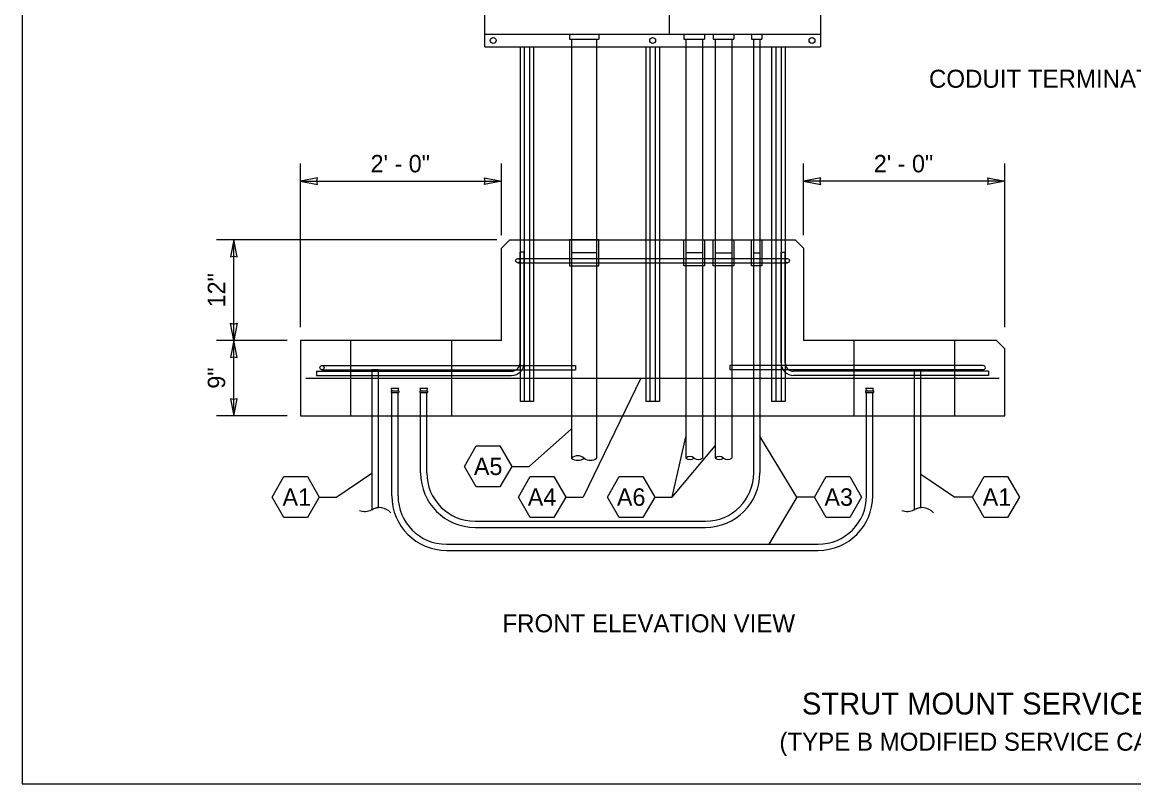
# Model space of a CAD drawing. Extents: x 99862 to 103151, y 100000 to 117076.
# Drawn here: x 99862 to 100882, y 103000 to 103698 of the extents above; entities that cross this region are included whole.
import ezdxf

# ---------------------------------------------------------------- set-up
doc = ezdxf.new("R2010")
doc.units = 0
for name, color, linetype in [('Default', 7, 'Continuous'), ('Level 1', 7, 'Continuous'), ('Level 11', 7, 'Continuous'), ('Level 15', 7, 'Continuous'), ('Level 20', 7, 'Continuous'), ('Level 40', 7, 'Continuous'), ('Level 60', 7, 'Continuous')]:
    doc.layers.add(name, color=color, linetype=linetype)

msp = doc.modelspace()

# ---------------------------------------------------------------- linework, layer by layer
at = {"layer": 'Default'}
for p, q in [((100316.7, 103481.1), (100564, 103481.1)), ((100318.7, 103385.5), (100318.7, 103486.9)), ((100322.5, 103486.9), (100318.7, 103486.9)), ((100322.5, 103385.5), (100322.5, 103486.9)), ((100558.2, 103385.5), (100558.2, 103486.9)), ((100558.2, 103486.9), (100562, 103486.9)), ((100562, 103385.5), (100562, 103486.9)), ((100316.7, 103477.2), (100564, 103477.2)), ((100132.1, 103377.9), (100132.1, 103374)), ((100132.1, 103377.9), (100311, 103377.9)), ((100137, 103383.1), (100369.5, 103383.1)), ((100137, 103379.2), (100369.5, 103379.2)), ((100369.5, 103383.1), (100369.5, 103379.2)), ((100511.2, 103383.1), (100511.2, 103379.2)), ((100743.7, 103383.1), (100511.2, 103383.1)), ((100743.7, 103379.2), (100511.2, 103379.2)), ((100748.6, 103377.9), (100569.7, 103377.9)), ((100748.6, 103377.9), (100748.6, 103374)), ((100132.1, 103374), (100311, 103374)), ((100748.6, 103374), (100569.7, 103374))]:
    msp.add_line(p, q, dxfattribs=at)
for centre in [(100316.7, 103479.2), (100564, 103479.2), (100137, 103381.1)]:
    msp.add_circle(centre, 1.92, dxfattribs=at)
for centre, radius, start, end in [((100311, 103385.5), 11.5, 270, 0), ((100311, 103385.5), 7.7, 270, 0), ((100569.7, 103385.5), 11.5, 180, 270), ((100569.7, 103385.5), 7.7, 180, 270), ((100743.7, 103381.1), 1.92, 270, 90)]:
    msp.add_arc(centre, radius, start, end, dxfattribs=at)
at = {"layer": 'Level 1'}
for p, q in [((100364, 103687), (100364, 103682.4)), ((100391, 103687), (100391, 103682.4)), ((100468.9, 103687), (100468.9, 103682.4)), ((100488.1, 103687), (100488.1, 103682.4)), ((100495.8, 103687), (100495.8, 103682.4)), ((100515, 103687), (100515, 103682.4)), ((100531.1, 103687), (100531.1, 103682.4)), ((100540.7, 103687), (100540.7, 103682.4)), ((100364, 103682.4), (100391, 103682.4)), ((100366, 103682.4), (100366, 103498.4)), ((100389, 103682.4), (100389, 103498.4)), ((100468.9, 103682.4), (100488.1, 103682.4)), ((100470.8, 103682.4), (100470.8, 103498.4)), ((100486.2, 103682.4), (100486.2, 103498.4)), ((100495.8, 103682.4), (100515, 103682.4)), ((100497.7, 103682.4), (100497.7, 103498.4)), ((100513.1, 103682.4), (100513.1, 103498.4)), ((100531.1, 103682.4), (100540.7, 103682.4)), ((100533, 103682.4), (100533, 103498.4)), ((100538.8, 103682.4), (100538.8, 103498.4)), ((100366, 103498.4), (100366, 103298.2)), ((100389, 103498.4), (100389, 103298.2)), ((100470.8, 103498.4), (100470.8, 103298.2)), ((100486.2, 103498.4), (100486.2, 103298.2)), ((100497.7, 103498.4), (100497.7, 103298.2)), ((100513.1, 103498.4), (100513.1, 103298.2)), ((100533, 103498.4), (100533, 103284.6)), ((100538.8, 103498.4), (100538.8, 103284.6)), ((100389, 103486.5), (100366, 103486.5)), ((100486.2, 103486.5), (100470.8, 103486.5)), ((100497.7, 103486.5), (100513.1, 103486.5)), ((100533, 103486.5), (100538.8, 103486.5)), ((100200.4, 103362.3), (100207.6, 103362.3)), ((100200.4, 103359.9), (100200.4, 103358.2)), ((100200.4, 103359.9), (100207.6, 103359.9)), ((100200.4, 103358.2), (100207.6, 103358.2)), ((100201.1, 103360.6), (100201.1, 103359.9)), ((100201.1, 103263.5), (100201.1, 103358.2)), ((100206.9, 103360.6), (100206.9, 103359.9)), ((100206.9, 103263.5), (100206.9, 103358.2)), ((100207.6, 103359.9), (100207.6, 103358.2)), ((100226.7, 103362.3), (100233.9, 103362.3)), ((100226.7, 103359.9), (100226.7, 103358.2)), ((100226.7, 103359.9), (100233.9, 103359.9)), ((100226.7, 103358.2), (100233.9, 103358.2)), ((100227.5, 103360.6), (100227.5, 103359.9)), ((100227.5, 103284.6), (100227.5, 103358.2)), ((100233.2, 103360.6), (100233.2, 103359.9)), ((100233.2, 103284.6), (100233.2, 103358.2)), ((100233.9, 103359.9), (100233.9, 103358.2)), ((100635.8, 103362.3), (100643, 103362.3)), ((100635.8, 103359.9), (100635.8, 103358.2)), ((100635.8, 103359.9), (100643, 103359.9)), ((100635.8, 103358.2), (100643, 103358.2)), ((100636.5, 103360.6), (100636.5, 103359.9)), ((100636.5, 103261.9), (100636.5, 103358.2)), ((100642.3, 103360.6), (100642.3, 103359.9)), ((100642.3, 103261.8), (100642.3, 103358.2)), ((100643, 103359.9), (100643, 103358.2)), ((100277.5, 103240.4), (100488.8, 103240.4)), ((100277.5, 103234.6), (100488.8, 103234.6)), ((100251.1, 103219.2), (100592.3, 103219.2)), ((100251.1, 103213.4), (100592.3, 103213.4))]:
    msp.add_line(p, q, dxfattribs=at)
for points in [[(99862, 102999.5), (103151, 102999.5), (103151, 105075.5), (99862, 105075.5)], [(100364, 103474.6), (100391, 103474.6), (100391, 103498.4), (100364, 103498.4)], [(100488.1, 103474.6), (100468.9, 103474.6), (100468.9, 103498.4), (100488.1, 103498.4)], [(100495.8, 103498.4), (100515, 103498.4), (100515, 103474.6), (100495.8, 103474.6)], [(100531.1, 103498.4), (100540.7, 103498.4), (100540.7, 103474.6), (100531.1, 103474.6)], [(100182.6, 103379.2), (100182.6, 103250.8), (100184.7, 103251.9), (100186.8, 103252.4), (100188.8, 103252.7), (100188.8, 103379.2)], [(100680.3, 103379.2), (100680.3, 103250.8), (100682.5, 103251.9), (100684.5, 103252.4), (100686.5, 103252.7), (100686.5, 103379.2)]]:
    msp.add_lwpolyline(points, close=True, dxfattribs=at)
for centre, radius, start, end in [((100198.7, 103360.6), 2.37, 0, 45.9402), ((100209.2, 103360.6), 2.37, 134.0598, 180), ((100225.1, 103360.6), 2.37, 0, 45.9402), ((100235.6, 103360.6), 2.37, 134.0598, 180), ((100634.2, 103360.6), 2.37, 0, 45.9402), ((100644.7, 103360.6), 2.37, 134.0598, 180), ((100371.7, 103291.1), 9.14, 50.8329, 129.1671), ((100371.7, 103305.3), 9.14, 230.8329, 309.1671), ((100383.3, 103305.3), 9.14, 230.8329, 309.1671), ((100474.7, 103293.5), 6.09, 50.8329, 129.1671), ((100474.7, 103302.9), 6.09, 230.8329, 309.1671), ((100482.4, 103302.9), 6.09, 230.8329, 309.1671), ((100501.5, 103293.5), 6.09, 50.8329, 129.1671), ((100501.5, 103302.9), 6.09, 230.8329, 309.1671), ((100509.2, 103302.9), 6.09, 230.8329, 309.1671), ((100277.5, 103284.6), 50, 180, 270), ((100277.5, 103284.6), 44.3, 180, 270), ((100488.8, 103284.6), 44.3, 270, 0), ((100488.8, 103284.6), 50, 270, 0), ((100251.1, 103263.5), 50, 180, 270), ((100251.1, 103263.5), 44.3, 180, 270), ((100592.3, 103263.5), 44.3, 270, 0), ((100592.3, 103263.5), 50, 270, 0), ((100176.2, 103263.9), 14.6, 250.7571, 295.3506), ((100189.8, 103238.6), 14.1, 42.3778, 121.1813), ((100673.9, 103263.9), 14.6, 250.7571, 295.3506), ((100687.5, 103238.6), 14.1, 42.3778, 121.1813)]:
    msp.add_arc(centre, radius, start, end, dxfattribs=at)
at = {"layer": 'Level 11'}
for p, q in [((100163.3, 103406.1), (100163.3, 103336.8)), ((100255.7, 103406.1), (100255.7, 103336.8)), ((100625, 103406.1), (100625, 103336.8)), ((100717.4, 103406.1), (100717.4, 103336.8))]:
    msp.add_line(p, q, dxfattribs=at)
for points in [[(100301.8, 103406.1), (100301.8, 103490.7), (100309.5, 103498.4)], [(100309.5, 103498.4), (100571.2, 103498.4)], [(100571.2, 103498.4), (100578.9, 103490.7), (100578.9, 103406.1)], [(100117.2, 103406.1), (100117.2, 103336.8)], [(100301.8, 103406.1), (100117.2, 103406.1)], [(100755.8, 103406.1), (100578.9, 103406.1)], [(100763.5, 103336.8), (100763.5, 103398.4), (100755.8, 103406.1)], [(100117.2, 103336.8), (100763.5, 103336.8)]]:
    msp.add_lwpolyline(points, dxfattribs=at)
at = {"layer": 'Level 15'}
for p, q in [((100117.2, 103418.1), (100117.2, 103568.2)), ((100301.8, 103502.7), (100301.8, 103568.2)), ((100578.9, 103502.7), (100578.9, 103568.2)), ((100763.5, 103418.1), (100763.5, 103568.2)), ((100117.2, 103552.2), (100301.8, 103552.2)), ((100763.5, 103552.2), (100578.9, 103552.2)), ((100297.5, 103498.4), (100040.2, 103498.4)), ((100056.2, 103406.1), (100056.2, 103498.4)), ((100105.2, 103406.1), (100040.2, 103406.1)), ((100056.2, 103336.8), (100056.2, 103406.1)), ((100429.5, 103371.4), (100376.6, 103262.4)), ((100105.2, 103336.8), (100040.2, 103336.8)), ((100327.1, 103290.6), (100366, 103324.9)), ((100458.3, 103262.4), (100470.8, 103317.6)), ((100572.8, 103262.4), (100538.8, 103318.4)), ((100458.3, 103262.4), (100497.7, 103309.3)), ((100311.1, 103290.6), (100327.1, 103290.6)), ((100182.6, 103283.9), (100150.5, 103262.4)), ((100686.5, 103283.3), (100717.7, 103262.4)), ((100134.5, 103262.4), (100150.5, 103262.4)), ((100360.6, 103262.4), (100376.6, 103262.4)), ((100442.3, 103262.4), (100458.3, 103262.4)), ((100572.8, 103262.4), (100547, 103219.2)), ((100588.8, 103262.4), (100572.8, 103262.4)), ((100733.7, 103262.4), (100717.7, 103262.4))]:
    msp.add_line(p, q, dxfattribs=at)
for points in [[(100117.2, 103552.2), (100132.9, 103549.2), (100132.2, 103552.2), (100132.9, 103555.3)], [(100301.8, 103552.2), (100286.1, 103549.2), (100286.8, 103552.2), (100286.1, 103555.3)], [(100578.9, 103552.2), (100594.6, 103549.2), (100593.9, 103552.2), (100594.6, 103555.3)], [(100763.5, 103552.2), (100747.8, 103549.2), (100748.5, 103552.2), (100747.8, 103555.3)], [(100056.2, 103498.4), (100053.1, 103482.7), (100056.2, 103483.4), (100059.3, 103482.7)], [(100056.2, 103406.1), (100053.1, 103421.8), (100056.2, 103421.1), (100059.3, 103421.8)], [(100056.2, 103406.1), (100053.1, 103390.3), (100056.2, 103391.1), (100059.3, 103390.3)], [(100056.2, 103336.8), (100059.3, 103352.5), (100056.2, 103351.8), (100053.1, 103352.5)]]:
    msp.add_lwpolyline(points, close=True, dxfattribs=at)
for centre in [(100294.1, 103681.2), (100440.4, 103681.2), (100586.6, 103681.2)]:
    msp.add_circle(centre, 2.69, dxfattribs=at)
at = {"layer": 'Level 20'}
for points in [[(100267.8, 103290.6), (100278.6, 103309.4), (100300.3, 103309.4), (100311.1, 103290.6), (100300.3, 103271.9), (100278.6, 103271.9), (100267.8, 103290.6)], [(100091.2, 103262.4), (100102.1, 103281.2), (100123.7, 103281.2), (100134.5, 103262.4), (100123.7, 103243.7), (100102.1, 103243.7), (100091.2, 103262.4)], [(100317.3, 103262.4), (100328.1, 103281.2), (100349.8, 103281.2), (100360.6, 103262.4), (100349.8, 103243.7), (100328.1, 103243.7), (100317.3, 103262.4)], [(100399, 103262.4), (100409.8, 103281.2), (100431.4, 103281.2), (100442.3, 103262.4), (100431.4, 103243.7), (100409.8, 103243.7), (100399, 103262.4)], [(100588.8, 103262.4), (100599.6, 103281.2), (100621.3, 103281.2), (100632.1, 103262.4), (100621.3, 103243.7), (100599.6, 103243.7), (100588.8, 103262.4)], [(100733.7, 103262.4), (100744.5, 103281.2), (100766.1, 103281.2), (100776.9, 103262.4), (100766.1, 103243.7), (100744.5, 103243.7), (100733.7, 103262.4)]]:
    msp.add_lwpolyline(points, dxfattribs=at)
at = {"layer": 'Level 40'}
for p, q in [((100286.5, 103675.4), (100286.5, 103987.1)), ((100455.7, 103687), (100455.7, 103987.1)), ((100594.3, 103987.1), (100594.3, 103675.4)), ((100286.5, 103687), (100594.3, 103687)), ((100286.5, 103675.4), (100594.3, 103675.4)), ((100318.7, 103675.4), (100318.7, 103498.4)), ((100322.5, 103675.4), (100322.5, 103498.4)), ((100327.4, 103675.4), (100327.4, 103498.4)), ((100331.2, 103675.4), (100331.2, 103498.4)), ((100434.1, 103675.4), (100434.1, 103498.4)), ((100437.9, 103675.4), (100437.9, 103498.4)), ((100442.8, 103675.4), (100442.8, 103498.4)), ((100446.6, 103675.4), (100446.6, 103498.4)), ((100549.4, 103675.4), (100549.4, 103498.4)), ((100553.3, 103675.4), (100553.3, 103498.4)), ((100558.2, 103675.4), (100558.2, 103498.4)), ((100562, 103675.4), (100562, 103498.4)), ((100318.7, 103498.4), (100318.7, 103350)), ((100322.5, 103498.4), (100322.5, 103350)), ((100327.4, 103498.4), (100327.4, 103350)), ((100331.2, 103498.4), (100331.2, 103350)), ((100434.1, 103498.4), (100434.1, 103350)), ((100437.9, 103498.4), (100437.9, 103350)), ((100442.8, 103498.4), (100442.8, 103350)), ((100446.6, 103498.4), (100446.6, 103350)), ((100549.4, 103498.4), (100549.4, 103350)), ((100553.3, 103498.4), (100553.3, 103350)), ((100558.2, 103498.4), (100558.2, 103350)), ((100562, 103498.4), (100562, 103350)), ((100122.3, 103371.4), (100758.4, 103371.4)), ((100331.2, 103350), (100318.7, 103350)), ((100446.6, 103350), (100434.1, 103350)), ((100562, 103350), (100549.4, 103350))]:
    msp.add_line(p, q, dxfattribs=at)
at = {"layer": 'Level 60'}
msp.add_line((99862, 102999.5), (99862, 102999.5), dxfattribs=at)

# ---------------------------------------------------------------- texts
at = {"layer": 'Level 20'}
for s, height, p in [('CODUIT TERMINATION DETAIL', 16.5, (100693.9, 103637.8)), ('2\' - 0"', 16, (100181.6, 103560.2)), ('2\' - 0"', 16, (100643.3, 103560.2)), ('A5', 16, (100276.4, 103282.6)), ('A1', 16, (100100.8, 103254.4)), ('A4', 16, (100325.8, 103254.4)), ('A6', 16, (100407.6, 103254.4)), ('A3', 16, (100598, 103254.4)), ('A1', 16, (100743.2, 103254.4)), ('FRONT ELEVATION VIEW', 16.5, (100302.6, 103138.4)), ('STRUT MOUNT SERVICE CABINET', 20, (100577.3, 103063)), ('(TYPE B MODIFIED SERVICE CABINET SHOWN)', 16.5, (100556.7, 103029.8))]:
    msp.add_text(s, height=height, dxfattribs=at).set_placement(p)
for s, p in [('12"', (100048.2, 103436.4)), ('9"', (100048.2, 103361.8))]:
    msp.add_text(s, height=16, rotation=90, dxfattribs=at).set_placement(p)

doc.saveas('drawing.dxf')
